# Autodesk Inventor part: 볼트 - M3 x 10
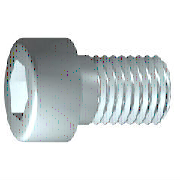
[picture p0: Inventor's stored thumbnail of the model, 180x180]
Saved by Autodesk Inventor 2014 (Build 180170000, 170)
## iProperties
Created: 2012-02
Part Number: 볼트 - M3 x 10
Material: 스테인리스강
Description: 6각 소켓 머리 캡 나사
Document SubType Name: Modeling
Standard: ISO 4762
Designer: mduedu
Standard Revision: Fourth edition 2004-03-01
Standards Organization: ISO
Language: ko-KR
Size Designation: M3 x 10
Categories: <MemberInstance><Categories><Category DisplayName="조임쇠" InternalName="e4da775c-781d-43d5-af7c-5136215cf5a6" Mnemonic="FSTN"><Category DisplayName="볼트" InternalN
Density: 8.08 g/cm^3
Appearance: 반광택
Mass: 1.0701 g
Surface Area: 2.01851 cm^2
Volume: 0.132438 cm^3
IsCustomPart: 0
Author: mduedu
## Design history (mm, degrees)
sketch "스케치1"
  geometry: L1 (-0.867, 0)-(10, 0); L2 (10, 0)-(10, 1.5); L3 (10, 1.5)-(1.25, 1.5); L4 (1.25, 1.5)-(0.943, 1.5); L5 (0.943, 1.5)-(0, 1.5); L6 (0, 1.5)-(0, 2.75); L7 (0, 2.75)-(-3, 2.75); L8 (-3, 2.75)-(-3, 1.443); L9 (-3, 1.443)-(-1.7, 1.443); L10 (-1.7, 1.443)-(-0.867, 0); L11 (-5.6, 0)-(12.6, 0) reference; L12 (0, -0.55)-(0, 3.3) reference; L13 (1.25, 1.5)-(0, 1.5)
  constraints: 22 end point, 6 parallel, 2 collinear, 2 perpendicular, 1 horizontal, 1 point on line
  dimensions: "d1" = 8.75 distance from line of L3.end L2 (= GEL); "d2" = 0.30683 distance of L4.end L3.end (computed from GAL); "d3" = 3 distance between parallel lines of L8 L6 (= KOH); "d4" = 1.3 distance of L8.end L9.end (= INTI); "d5" = 60 deg angle of L10 L1; "d6" = 3 diameter of L3 L1 (= GD); "d7" = 3 diameter of L5 L1 (= BDM); "d8" = 2.88675 diameter of L9 L1 (= 1.1547 x SW); "d9" = 5.5 diameter of L7 L1 (= KOD); "d26" = 10 distance between parallel lines of L12 L2 (= NLG)
revolve "본체" sketch "스케치1" stored, may be unused: angle "d10" = 90 deg
sketch "스케치2"
  geometry: L1 (0, -3.85)-(0, 3.85) reference; L2 (-3.85, 0)-(3.85, 0) reference; L3 (1.443, 0)-(0.722, -1.25); L4 (0.722, -1.25)-(-0.722, -1.25); L5 (-0.722, -1.25)-(-1.443, 0); L6 (-1.443, 0)-(-0.722, 1.25); L7 (-0.722, 1.25)-(0.722, 1.25); L8 (0.722, 1.25)-(1.443, 0); 2 further points
  constraints: 12 end point, 1 coincident, 1 horizontal alignment, 1 point on line, 12 other
extrude "슬롯" join sketch "스케치2" stored distance "d11" = 10; taper "d12" = 0 deg
workplane "Work Plane1"
fillet "Fillet2" dims "d30" = 0.1 (= R)
body "Solid1"
fillet "모깎기1" dims "d17" = 0.3 (= RR)
feature "스레드" dims "d13" = 8.75 (= GEL), "d14" = 0
chamfer "모따기1" distance "d15" = 0.30673 (= -0.5 x SPD + 0.5 x GD); stored, may be unused: second distance "d16" = 0.30673 (= GUL), angle "d27" = 45 deg
other parameters: "GD" = 3 [user parameter; used in 2 equation terms], "NLG" = 10 [user parameter; used in 1 equation term], "GEL" = 8.75 [user parameter; used in 2 equation terms], "KOD" = 5.5 [user parameter; used in 1 equation term], "KOH" = 3 [user parameter; used in 1 equation term], "INTI" = 1.3 [user parameter; used in 1 equation term], "GAL" = 0.30673 (= 0.61345 x PTC) [user parameter; used in 1 equation term], "GUL" = 0.30673 (= 0.61345 x PTC) [user parameter; used in 1 equation term], "BDM" = 3 (= NND) [user parameter; used in 1 equation term], "SW" = 2.5 [user parameter; used in 2 equation terms], "RR" = 0.3 [user parameter; used in 1 equation term], "SPD" = 2.38655 (= NND - 1.2269 x PTC) [user parameter; used in 1 equation term], "d19" = 0, "d28" = 0, "d29" = 0, "R" = 0.1 [user parameter; used in 1 equation term], "TOA" = 30 deg [user parameter], "GD1" = 2.38655 (= THREADDIA - 1.2269 x PTC) [user parameter], "THREADDIA" = 3 [user parameter; used in 1 equation term], "FAWI" = 45 deg [user parameter], "PTC" = 0.5 [user parameter; used in 5 equation terms], "NND" = 3 [user parameter; used in 2 equation terms], "E0" = 2.8875 (= 1.155 x SW) [user parameter]
